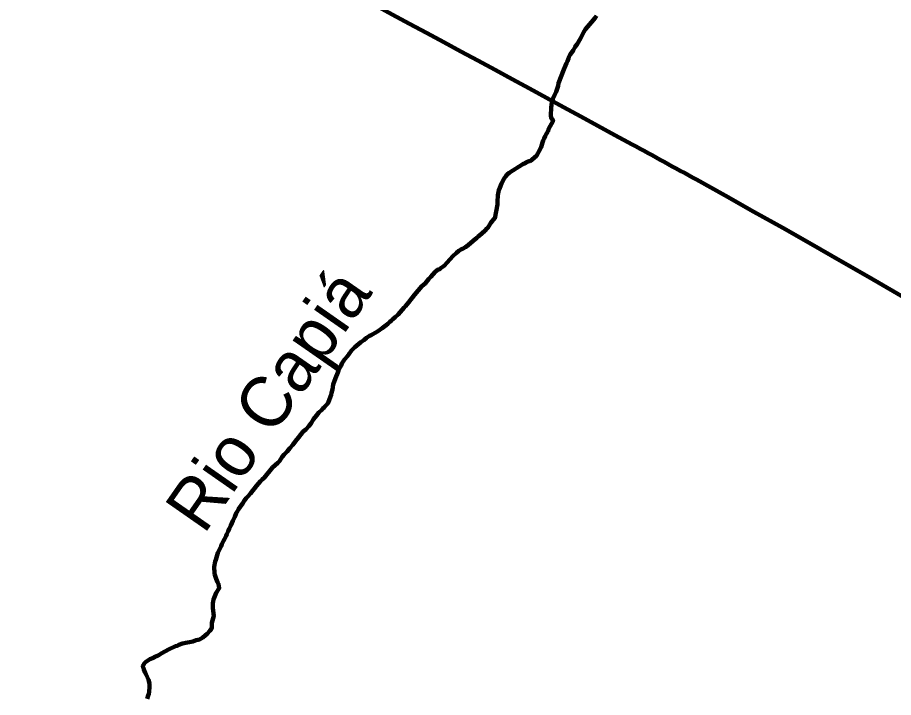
# Model space of a CAD drawing. Extents: x 553962 to 842807, y 8883888 to 9032388.
# Drawn here: x 646431 to 655119, y 8959925 to 8966671 of the extents above; entities that cross this region are included whole.
import ezdxf
from ezdxf.enums import TextEntityAlignment as Align

# ---------------------------------------------------------------- set-up
doc = ezdxf.new("R2010")
doc.units = 0
doc.header["$LTSCALE"] = 200
doc.linetypes.add('DASH_DOUBLE_DOT', pattern=[9.2, 5, -1.2, 0.3, -1.2, 0.3, -1.2])
for name, color, linetype, lineweight in [('11', 7, 'DASH_DOUBLE_DOT', 106), ('24', 7, 'Continuous', 25), ('9', 7, 'Continuous', 90)]:
    doc.layers.add(name, color=color, linetype=linetype, lineweight=lineweight)
doc.layers.add('49', color=7, linetype='Continuous')

msp = doc.modelspace()

# ---------------------------------------------------------------- linework, layer by layer
at = {"layer": '11'}
for points in [[(652174.8, 8966688.9), (652160.4, 8966666.8), (652125.1, 8966623.9), (652084.5, 8966580), (652063.4, 8966553.7), (652047.7, 8966528.9), (652014.7, 8966461.6), (651981.7, 8966407.3), (651960.2, 8966375.4), (651944.1, 8966347.6), (651912.1, 8966302.5), (651898.2, 8966276.2), (651897.4, 8966264.9), (651885.1, 8966236.2), (651874.7, 8966216.8), (651867.7, 8966193.9), (651851, 8966156.5), (651798.1, 8966019.3), (651792.6, 8965994.6), (651772.9, 8965932.8), (651759.8, 8965907.9), (651741.4, 8965863.8), (651729.4, 8965826.5), (651723.3, 8965779.3), (651720.3, 8965699.1), (651722.8, 8965675), (651743.5, 8965648.6), (651743.4, 8965644.6), (651698.9, 8965564), (651693.6, 8965544.1), (651688.2, 8965540.4), (651686.5, 8965534.9), (651674.3, 8965514.2), (651664.3, 8965494.4), (651655.9, 8965471.5), (651645.4, 8965450), (651637.1, 8965429.3), (651623.4, 8965385), (651601.4, 8965342.9), (651591.7, 8965321.5), (651577.2, 8965299.5), (651559.6, 8965280.8), (651533.4, 8965257.4), (651515.3, 8965247.1), (651499.6, 8965244.2), (651496.3, 8965241.1), (651479.6, 8965235.3), (651466.6, 8965226.9), (651443.2, 8965217.1), (651307.6, 8965130.1), (651287.6, 8965112.6), (651272.7, 8965096.7), (651258.7, 8965075.1), (651231.1, 8965023.9), (651213.3, 8964982.5), (651203.9, 8964956.5), (651195.2, 8964907.3), (651191.2, 8964841.6), (651191, 8964817.2), (651164.9, 8964678.6), (651157.3, 8964676.2), (651155.4, 8964668.4), (651148.9, 8964664.2), (651138.2, 8964651.3), (651124.9, 8964632.4), (651105.4, 8964599.6), (651094.6, 8964583.9), (651089.5, 8964580.2), (651065.3, 8964555.2), (651012.9, 8964509), (650998.5, 8964498.8), (650986.4, 8964486.1), (650949.3, 8964456), (650900.6, 8964412.3), (650874.5, 8964393.6), (650844.8, 8964377.2), (650826.4, 8964368.8), (650809.3, 8964357.4), (650785.7, 8964337.7), (650747.8, 8964302.8), (650693.7, 8964240.3), (650662, 8964208.7), (650662, 8964208.7), (650632.1, 8964188.2), (650618, 8964175.7), (650604.2, 8964169.9), (650589.6, 8964160.3)], [(650589.6, 8964160.3), (650574.3, 8964146.5), (650530.2, 8964098.3), (650509, 8964077.9), (650473.5, 8964033), (650442.6, 8964005.1), (650368.1, 8963919.8), (650346, 8963888.5), (650332.8, 8963874.9), (650310.5, 8963845.9), (650278.5, 8963808.1), (650264.2, 8963793.4), (650207.7, 8963725.5), (650176.4, 8963697.3), (650153.9, 8963678.9), (650140.4, 8963665.7), (650124.7, 8963653.2), (650103.3, 8963631.9), (650086.5, 8963618), (650072.4, 8963608.2), (650060.6, 8963597.7), (650046.6, 8963590.1), (650000.4, 8963555.6), (649955.2, 8963530.6), (649939, 8963520), (649922.4, 8963511.9), (649893.1, 8963492), (649865.1, 8963469.6), (649835.2, 8963451.3), (649777.6, 8963401.4), (649742.6, 8963367.3), (649718.9, 8963335.7), (649704, 8963312.6), (649674.6, 8963276.8), (649661.2, 8963257.8), (649648.9, 8963237.2), (649640.8, 8963219.3), (649630.7, 8963202.8), (649615, 8963169.3), (649608.8, 8963150.8), (649584.8, 8963092.3), (649563.2, 8963031.5), (649555.5, 8962980.1), (649545.2, 8962946.6), (649541.4, 8962928), (649515.6, 8962859.5), (649507.1, 8962843.2), (649499.9, 8962833.4), (649481.2, 8962814.6), (649475.3, 8962806.6), (649456.2, 8962788.3), (649449.4, 8962778.8), (649420.2, 8962753.5), (649395, 8962724.1), (649367.2, 8962685.5), (649343.5, 8962648.1), (649319.4, 8962615.6), (649289.5, 8962584.5), (649264.9, 8962562.7), (649217.7, 8962504.2), (649187.2, 8962469.5), (649162, 8962433.2), (649131.5, 8962399.3), (649105.7, 8962365.4), (649075.9, 8962335.3), (649056.5, 8962311.9), (649027.9, 8962268.9), (649013.5, 8962252.7), (648961.3, 8962205.6), (648876.1, 8962105.7), (648858.3, 8962087.9), (648839.2, 8962071.7), (648801.6, 8962026.5), (648742.1, 8961950.5), (648715.9, 8961919), (648698.4, 8961903), (648678.4, 8961875.1), (648665.1, 8961852.7), (648623.9, 8961794), (648612.1, 8961775.1), (648600.3, 8961752.7), (648585.9, 8961717.7), (648566.1, 8961679.4), (648547.4, 8961632), (648528.6, 8961598.4), (648520.4, 8961575.2), (648506.1, 8961547), (648501.5, 8961529.9), (648482.2, 8961497.1), (648474.8, 8961478.5), (648456.4, 8961445.7), (648449.2, 8961427.1), (648419.2, 8961360.9), (648410.6, 8961337.9), (648398, 8961290.7), (648391.5, 8961272.8), (648380.9, 8961222.2), (648380.9, 8961222.2), (648379.8, 8961206.8), (648384.7, 8961171.6), (648385.1, 8961152.9)], [(648385.1, 8961152.9), (648390, 8961133.3), (648400.4, 8961103), (648415.7, 8961067.9), (648425.4, 8961050), (648432.1, 8961011), (648401.9, 8960963.6), (648376.2, 8960898.2), (648370.1, 8960878.6), (648367.8, 8960859.9), (648367.9, 8960810.1), (648376.5, 8960734.5), (648357.4, 8960665.8), (648358.8, 8960619.8), (648351.9, 8960604.5), (648338.8, 8960585.2), (648311.2, 8960556.4), (648291.8, 8960541.2), (648269.8, 8960521), (648236.7, 8960501.1), (648220, 8960496.4), (648202.2, 8960494.8), (648170.1, 8960481.9), (648153, 8960477.4), (648100.1, 8960468.4), (648066.6, 8960460), (648032.2, 8960447.3), (648014.3, 8960438.5), (647997.2, 8960433), (647928.7, 8960400.9), (647863.5, 8960365.3), (647826.2, 8960342.8), (647793.8, 8960329), (647778, 8960318.3), (647744.3, 8960305.3), (647701.1, 8960277.2), (647689.4, 8960265.4), (647679.9, 8960250.9), (647675, 8960238.2), (647674.2, 8960228.6), (647680.1, 8960220.4), (647683.5, 8960203.8), (647689.9, 8960186.8), (647698.1, 8960170.3), (647708.3, 8960153.8), (647730.9, 8960100.4), (647739.1, 8960063.9), (647740.2, 8960032), (647736.1, 8959980.6), (647731.8, 8959962.6), (647725, 8959943.9), (647716.7, 8959911.2)]]:
    msp.add_lwpolyline(points, dxfattribs=at)
at = {"layer": '24', "lineweight": 53}
for points in [[(652174.8, 8966688.9), (652160.4, 8966666.8), (652125.1, 8966623.9), (652084.5, 8966580), (652063.4, 8966553.7), (652047.7, 8966528.9), (652014.7, 8966461.6), (651981.7, 8966407.3), (651960.2, 8966375.4), (651944.1, 8966347.6), (651912.1, 8966302.5), (651898.2, 8966276.2), (651897.4, 8966264.9), (651885.1, 8966236.2), (651874.7, 8966216.8), (651867.7, 8966193.9), (651851, 8966156.5), (651798.1, 8966019.3), (651792.6, 8965994.6), (651772.9, 8965932.8), (651759.8, 8965907.9), (651741.4, 8965863.8), (651729.4, 8965826.5), (651723.3, 8965779.3), (651720.3, 8965699.1), (651722.8, 8965675), (651743.5, 8965648.6), (651743.4, 8965644.6), (651698.9, 8965564), (651693.6, 8965544.1), (651688.2, 8965540.4), (651686.5, 8965534.9), (651674.3, 8965514.2), (651664.3, 8965494.4), (651655.9, 8965471.5), (651645.4, 8965450), (651637.1, 8965429.3), (651623.4, 8965385), (651601.4, 8965342.9), (651591.7, 8965321.5), (651577.2, 8965299.5), (651559.6, 8965280.8), (651533.4, 8965257.4), (651515.3, 8965247.1), (651499.6, 8965244.2), (651496.3, 8965241.1), (651479.6, 8965235.3), (651466.6, 8965226.9), (651443.2, 8965217.1), (651307.6, 8965130.1), (651287.6, 8965112.6), (651272.7, 8965096.7), (651258.7, 8965075.1), (651231.1, 8965023.9), (651213.3, 8964982.5), (651203.9, 8964956.5), (651195.2, 8964907.3), (651191.2, 8964841.6), (651191, 8964817.2), (651164.9, 8964678.6), (651157.3, 8964676.2), (651155.4, 8964668.4), (651148.9, 8964664.2), (651138.2, 8964651.3), (651124.9, 8964632.4), (651105.4, 8964599.6), (651094.6, 8964583.9), (651089.5, 8964580.2), (651065.3, 8964555.2), (651012.9, 8964509), (650998.5, 8964498.8), (650986.4, 8964486.1), (650949.3, 8964456), (650900.6, 8964412.3), (650874.5, 8964393.6), (650844.8, 8964377.2), (650826.4, 8964368.8), (650809.3, 8964357.4), (650785.7, 8964337.7), (650747.8, 8964302.8), (650693.7, 8964240.3), (650662, 8964208.7), (650662, 8964208.7), (650632.1, 8964188.2), (650618, 8964175.7), (650604.2, 8964169.9), (650589.6, 8964160.3)], [(650589.6, 8964160.3), (650574.3, 8964146.5), (650530.2, 8964098.3), (650509, 8964077.9), (650473.5, 8964033), (650442.6, 8964005.1), (650368.1, 8963919.8), (650346, 8963888.5), (650332.8, 8963874.9), (650310.5, 8963845.9), (650278.5, 8963808.1), (650264.2, 8963793.4), (650207.7, 8963725.5), (650176.4, 8963697.3), (650153.9, 8963678.9), (650140.4, 8963665.7), (650124.7, 8963653.2), (650103.3, 8963631.9), (650086.5, 8963618), (650072.4, 8963608.2), (650060.6, 8963597.7), (650046.6, 8963590.1), (650000.4, 8963555.6), (649955.2, 8963530.6), (649939, 8963520), (649922.4, 8963511.9), (649893.1, 8963492), (649865.1, 8963469.6), (649835.2, 8963451.3), (649777.6, 8963401.4), (649742.6, 8963367.3), (649718.9, 8963335.7), (649704, 8963312.6), (649674.6, 8963276.8), (649661.2, 8963257.8), (649648.9, 8963237.2), (649640.8, 8963219.3), (649630.7, 8963202.8), (649615, 8963169.3), (649608.8, 8963150.8), (649584.8, 8963092.3), (649563.2, 8963031.5), (649555.5, 8962980.1), (649545.2, 8962946.6), (649541.4, 8962928), (649515.6, 8962859.5), (649507.1, 8962843.2), (649499.9, 8962833.4), (649481.2, 8962814.6), (649475.3, 8962806.6), (649456.2, 8962788.3), (649449.4, 8962778.8), (649420.2, 8962753.5), (649395, 8962724.1), (649367.2, 8962685.5), (649343.5, 8962648.1), (649319.4, 8962615.6), (649289.5, 8962584.5), (649264.9, 8962562.7), (649217.7, 8962504.2), (649187.2, 8962469.5), (649162, 8962433.2), (649131.5, 8962399.3), (649105.7, 8962365.4), (649075.9, 8962335.3), (649056.5, 8962311.9), (649027.9, 8962268.9), (649013.5, 8962252.7), (648961.3, 8962205.6), (648876.1, 8962105.7), (648858.3, 8962087.9), (648839.2, 8962071.7), (648801.6, 8962026.5), (648742.1, 8961950.5), (648715.9, 8961919), (648698.4, 8961903), (648678.4, 8961875.1), (648665.1, 8961852.7), (648623.9, 8961794), (648612.1, 8961775.1), (648600.3, 8961752.7), (648585.9, 8961717.7), (648566.1, 8961679.4), (648547.4, 8961632), (648528.6, 8961598.4), (648520.4, 8961575.2), (648506.1, 8961547), (648501.5, 8961529.9), (648482.2, 8961497.1), (648474.8, 8961478.5), (648456.4, 8961445.7), (648449.2, 8961427.1), (648419.2, 8961360.9), (648410.6, 8961337.9), (648398, 8961290.7), (648391.5, 8961272.8), (648380.9, 8961222.2), (648380.9, 8961222.2), (648379.8, 8961206.8), (648384.7, 8961171.6), (648385.1, 8961152.9)], [(648385.1, 8961152.9), (648390, 8961133.3), (648400.4, 8961103), (648415.7, 8961067.9), (648425.4, 8961050), (648432.1, 8961011), (648401.9, 8960963.6), (648376.2, 8960898.2), (648370.1, 8960878.6), (648367.8, 8960859.9), (648367.9, 8960810.1), (648376.5, 8960734.5), (648357.4, 8960665.8), (648358.8, 8960619.8), (648351.9, 8960604.5), (648338.8, 8960585.2), (648311.2, 8960556.4), (648291.8, 8960541.2), (648269.8, 8960521), (648236.7, 8960501.1), (648220, 8960496.4), (648202.2, 8960494.8), (648170.1, 8960481.9), (648153, 8960477.4), (648100.1, 8960468.4), (648066.6, 8960460), (648032.2, 8960447.3), (648014.3, 8960438.5), (647997.2, 8960433), (647928.7, 8960400.9), (647863.5, 8960365.3), (647826.2, 8960342.8), (647793.8, 8960329), (647778, 8960318.3), (647744.3, 8960305.3), (647701.1, 8960277.2), (647689.4, 8960265.4), (647679.9, 8960250.9), (647675, 8960238.2), (647674.2, 8960228.6), (647680.1, 8960220.4), (647683.5, 8960203.8), (647689.9, 8960186.8), (647698.1, 8960170.3), (647708.3, 8960153.8), (647730.9, 8960100.4), (647739.1, 8960063.9), (647740.2, 8960032), (647736.1, 8959980.6), (647731.8, 8959962.6), (647725, 8959943.9), (647716.7, 8959911.2)]]:
    msp.add_lwpolyline(points, dxfattribs=at)
at = {"layer": '9'}
for points in [[(652174.8, 8966688.9), (652160.4, 8966666.8), (652125.1, 8966623.9), (652084.5, 8966580), (652063.4, 8966553.7), (652047.7, 8966528.9), (652014.7, 8966461.6), (651981.7, 8966407.3), (651960.2, 8966375.4), (651944.1, 8966347.6), (651912.1, 8966302.5), (651898.2, 8966276.2), (651897.4, 8966264.9), (651885.1, 8966236.2), (651874.7, 8966216.8), (651867.7, 8966193.9), (651851, 8966156.5), (651798.1, 8966019.3), (651792.6, 8965994.6), (651772.9, 8965932.8), (651759.8, 8965907.9), (651741.4, 8965863.8), (651729.4, 8965826.5), (651723.3, 8965779.3), (651720.3, 8965699.1), (651722.8, 8965675), (651743.5, 8965648.6), (651743.4, 8965644.6), (651698.9, 8965564), (651693.6, 8965544.1), (651688.2, 8965540.4), (651686.5, 8965534.9), (651674.3, 8965514.2), (651664.3, 8965494.4), (651655.9, 8965471.5), (651645.4, 8965450), (651637.1, 8965429.3), (651623.4, 8965385), (651601.4, 8965342.9), (651591.7, 8965321.5), (651577.2, 8965299.5), (651559.6, 8965280.8), (651533.4, 8965257.4), (651515.3, 8965247.1), (651499.6, 8965244.2), (651496.3, 8965241.1), (651479.6, 8965235.3), (651466.6, 8965226.9), (651443.2, 8965217.1), (651307.6, 8965130.1), (651287.6, 8965112.6), (651272.7, 8965096.7), (651258.7, 8965075.1), (651231.1, 8965023.9), (651213.3, 8964982.5), (651203.9, 8964956.5), (651195.2, 8964907.3), (651191.2, 8964841.6), (651191, 8964817.2), (651164.9, 8964678.6), (651157.3, 8964676.2), (651155.4, 8964668.4), (651148.9, 8964664.2), (651138.2, 8964651.3), (651124.9, 8964632.4), (651105.4, 8964599.6), (651094.6, 8964583.9), (651089.5, 8964580.2), (651065.3, 8964555.2), (651012.9, 8964509), (650998.5, 8964498.8), (650986.4, 8964486.1), (650949.3, 8964456), (650900.6, 8964412.3), (650874.5, 8964393.6), (650844.8, 8964377.2), (650826.4, 8964368.8), (650809.3, 8964357.4), (650785.7, 8964337.7), (650747.8, 8964302.8), (650693.7, 8964240.3), (650662, 8964208.7), (650662, 8964208.7), (650632.1, 8964188.2), (650618, 8964175.7), (650604.2, 8964169.9), (650589.6, 8964160.3)], [(650589.6, 8964160.3), (650574.3, 8964146.5), (650530.2, 8964098.3), (650509, 8964077.9), (650473.5, 8964033), (650442.6, 8964005.1), (650368.1, 8963919.8), (650346, 8963888.5), (650332.8, 8963874.9), (650310.5, 8963845.9), (650278.5, 8963808.1), (650264.2, 8963793.4), (650207.7, 8963725.5), (650176.4, 8963697.3), (650153.9, 8963678.9), (650140.4, 8963665.7), (650124.7, 8963653.2), (650103.3, 8963631.9), (650086.5, 8963618), (650072.4, 8963608.2), (650060.6, 8963597.7), (650046.6, 8963590.1), (650000.4, 8963555.6), (649955.2, 8963530.6), (649939, 8963520), (649922.4, 8963511.9), (649893.1, 8963492), (649865.1, 8963469.6), (649835.2, 8963451.3), (649777.6, 8963401.4), (649742.6, 8963367.3), (649718.9, 8963335.7), (649704, 8963312.6), (649674.6, 8963276.8), (649661.2, 8963257.8), (649648.9, 8963237.2), (649640.8, 8963219.3), (649630.7, 8963202.8), (649615, 8963169.3), (649608.8, 8963150.8), (649584.8, 8963092.3), (649563.2, 8963031.5), (649555.5, 8962980.1), (649545.2, 8962946.6), (649541.4, 8962928), (649515.6, 8962859.5), (649507.1, 8962843.2), (649499.9, 8962833.4), (649481.2, 8962814.6), (649475.3, 8962806.6), (649456.2, 8962788.3), (649449.4, 8962778.8), (649420.2, 8962753.5), (649395, 8962724.1), (649367.2, 8962685.5), (649343.5, 8962648.1), (649319.4, 8962615.6), (649289.5, 8962584.5), (649264.9, 8962562.7), (649217.7, 8962504.2), (649187.2, 8962469.5), (649162, 8962433.2), (649131.5, 8962399.3), (649105.7, 8962365.4), (649075.9, 8962335.3), (649056.5, 8962311.9), (649027.9, 8962268.9), (649013.5, 8962252.7), (648961.3, 8962205.6), (648876.1, 8962105.7), (648858.3, 8962087.9), (648839.2, 8962071.7), (648801.6, 8962026.5), (648742.1, 8961950.5), (648715.9, 8961919), (648698.4, 8961903), (648678.4, 8961875.1), (648665.1, 8961852.7), (648623.9, 8961794), (648612.1, 8961775.1), (648600.3, 8961752.7), (648585.9, 8961717.7), (648566.1, 8961679.4), (648547.4, 8961632), (648528.6, 8961598.4), (648520.4, 8961575.2), (648506.1, 8961547), (648501.5, 8961529.9), (648482.2, 8961497.1), (648474.8, 8961478.5), (648456.4, 8961445.7), (648449.2, 8961427.1), (648419.2, 8961360.9), (648410.6, 8961337.9), (648398, 8961290.7), (648391.5, 8961272.8), (648380.9, 8961222.2), (648380.9, 8961222.2), (648379.8, 8961206.8), (648384.7, 8961171.6), (648385.1, 8961152.9)], [(648385.1, 8961152.9), (648390, 8961133.3), (648400.4, 8961103), (648415.7, 8961067.9), (648425.4, 8961050), (648432.1, 8961011), (648401.9, 8960963.6), (648376.2, 8960898.2), (648370.1, 8960878.6), (648367.8, 8960859.9), (648367.9, 8960810.1), (648376.5, 8960734.5), (648357.4, 8960665.8), (648358.8, 8960619.8), (648351.9, 8960604.5), (648338.8, 8960585.2), (648311.2, 8960556.4), (648291.8, 8960541.2), (648269.8, 8960521), (648236.7, 8960501.1), (648220, 8960496.4), (648202.2, 8960494.8), (648170.1, 8960481.9), (648153, 8960477.4), (648100.1, 8960468.4), (648066.6, 8960460), (648032.2, 8960447.3), (648014.3, 8960438.5), (647997.2, 8960433), (647928.7, 8960400.9), (647863.5, 8960365.3), (647826.2, 8960342.8), (647793.8, 8960329), (647778, 8960318.3), (647744.3, 8960305.3), (647701.1, 8960277.2), (647689.4, 8960265.4), (647679.9, 8960250.9), (647675, 8960238.2), (647674.2, 8960228.6), (647680.1, 8960220.4), (647683.5, 8960203.8), (647689.9, 8960186.8), (647698.1, 8960170.3), (647708.3, 8960153.8), (647730.9, 8960100.4), (647739.1, 8960063.9), (647740.2, 8960032), (647736.1, 8959980.6), (647731.8, 8959962.6), (647725, 8959943.9), (647716.7, 8959911.2)]]:
    msp.add_lwpolyline(points, dxfattribs=at)
msp.add_spline([(637260.6, 8972975.8), (641524.5, 8971056.2), (652526.1, 8965412.7), (653164.3, 8965062.8), (670790.5, 8953770.1), (686194, 8943929.9), (696283.3, 8937647.1)], degree=3, dxfattribs=at)

# ---------------------------------------------------------------- texts
at = {"layer": '49'}
msp.add_text('Rio Capiá', height=500, rotation=55.114, dxfattribs=at).set_placement((649119.7, 8962738.4), align=Align.CENTER)

doc.saveas('drawing.dxf')
